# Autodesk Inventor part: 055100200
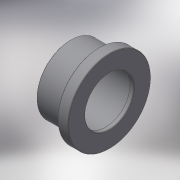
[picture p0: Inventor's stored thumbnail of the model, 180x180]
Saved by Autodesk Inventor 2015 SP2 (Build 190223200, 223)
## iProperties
Created: 2017-10
Part Number: 055100200
Material: Generic
Description: PLASSON FLANGE FLAT AD.-CEM 200
Document SubType Name: Modeling
Designer: KIM
Mass: 1269.68 g
Surface Area: 2003.25 cm^2
Volume: 1269.68 cm^3
Density: 1 g/cm^3
Appearance: Default
Author: KIM
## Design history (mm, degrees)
derived "055100.ipt"
feature "Solid1::055100.ipt"
tag "TaggingFeature1"
body "Solid1"
other parameters: "d0" = 113, "d1" = 228, "d4" = 17, "d5" = 106, "d6" = 254, "d8" = 2, "E_" = 228, "E_1" = 254, "l_" = 106, "B_" = 17, "H_" = 113
